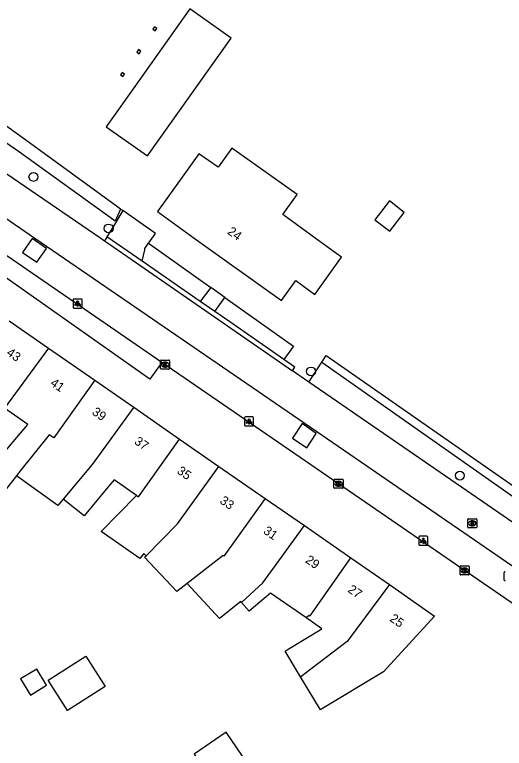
# Model space of a CAD drawing. Extents: x 163863 to 164644, y 379566 to 382155.
# Drawn here: x 164350.3 to 164404.5, y 381693.6 to 381774.7 of the extents above; entities that cross this region are included whole.
import ezdxf

# ---------------------------------------------------------------- set-up
doc = ezdxf.new("R2010")
doc.units = 0
for name, color, linetype in [('IMGEO_Boom', 7, 'Continuous'), ('IMGEO_Brandkraan', 7, 'Continuous'), ('IMGEO_Groenvoorziening', 7, 'Continuous'), ('IMGEO_Kolk', 7, 'Continuous'), ('IMGEO_Lichtpunt', 7, 'Continuous'), ('IMGEO_Pand', 7, 'Continuous'), ('IMGEO_Pand_nummerreeks', 7, 'Continuous'), ('IMGEO_Parkeervlak_open', 7, 'Continuous'), ('IMGEO_Rijbaan_lokaal_gesloten', 7, 'Continuous'), ('IMGEO_Rijbaan_lokaal_open', 7, 'Continuous'), ('IMGEO_Rioolput', 7, 'Continuous'), ('IMGEO_Voetpad_halfverhard', 7, 'Continuous'), ('IMGEO_Voetpad_open', 7, 'Continuous'), ('IMGEO_Waterloop', 7, 'Continuous')]:
    doc.layers.add(name, color=color, linetype=linetype)

msp = doc.modelspace()

# ---------------------------------------------------------------- linework, layer by layer
at = {"layer": 'IMGEO_Boom'}
for centre in [(164352.371, 381756.76), (164360.689, 381751.063), (164383.081, 381735.243), (164399.541, 381723.722)]:
    msp.add_circle(centre, 0.489, dxfattribs=at)
at = {"layer": 'IMGEO_Brandkraan'}
msp.add_line((164404.464, 381712.158), (164404.464, 381713.01), dxfattribs=at)
msp.add_lwpolyline([(164404.464, 381712.158), (164404.464, 381713.01)], dxfattribs=at)
for centre, start, end in [((164404.541, 381713.008), 91.55205, 178.44795), ((164404.541, 381713.008), 91.55205, 178.44795), ((164404.541, 381712.16), 181.55205, 268.44795), ((164404.541, 381712.16), 181.55205, 268.44795)]:
    msp.add_arc(centre, 0.0765, start, end, dxfattribs=at)
at = {"layer": 'IMGEO_Groenvoorziening'}
for points in [[(164362.264, 381753.03), (164362.019, 381753.203)], [(164365.11, 381749.429), (164371.983, 381744.544)], [(164373.541, 381743.437), (164381.128, 381738.044), (164380.075, 381736.577)], [(164382.848, 381734.057), (164384.279, 381736.27)]]:
    msp.add_lwpolyline(points, dxfattribs=at)
at = {"layer": 'IMGEO_Kolk'}
for p, q in [((164366.513, 381736.505), (164367.365, 381736.505)), ((164366.438, 381735.579), (164366.438, 381736.431)), ((164366.949, 381735.725), (164366.924, 381735.725)), ((164366.926, 381736.285), (164366.951, 381736.285)), ((164367.439, 381736.431), (164367.439, 381735.579)), ((164367.365, 381735.505), (164366.513, 381735.505)), ((164385.621, 381722.391), (164385.621, 381723.243)), ((164385.696, 381723.317), (164386.548, 381723.317)), ((164386.109, 381723.097), (164386.134, 381723.097)), ((164386.622, 381723.243), (164386.622, 381722.391)), ((164386.548, 381722.317), (164385.696, 381722.317)), ((164386.132, 381722.537), (164386.107, 381722.537)), ((164399.638, 381713.731), (164400.49, 381713.731)), ((164399.563, 381712.805), (164399.563, 381713.657)), ((164400.074, 381712.951), (164400.049, 381712.951)), ((164400.051, 381713.511), (164400.076, 381713.511)), ((164400.564, 381713.657), (164400.564, 381712.805)), ((164400.49, 381712.731), (164399.638, 381712.731))]:
    msp.add_line(p, q, dxfattribs=at)
for points in [[(164366.513, 381736.505), (164367.365, 381736.505)], [(164366.438, 381735.579), (164366.438, 381736.431)], [(164366.759, 381736.205), (164366.882, 381736.205), (164366.882, 381736.054), (164367.012, 381736.205), (164367.176, 381736.205), (164367.03, 381736.054), (164367.183, 381735.805), (164367.031, 381735.805), (164366.946, 381735.969), (164366.882, 381735.902), (164366.882, 381735.805), (164366.759, 381735.805), (164366.759, 381736.205)], [(164367.439, 381736.431), (164367.439, 381735.579)], [(164367.365, 381735.505), (164366.513, 381735.505)], [(164385.621, 381722.391), (164385.621, 381723.243)], [(164385.696, 381723.317), (164386.548, 381723.317)], [(164385.942, 381723.017), (164386.065, 381723.017), (164386.065, 381722.866), (164386.195, 381723.017), (164386.359, 381723.017), (164386.213, 381722.866), (164386.366, 381722.617), (164386.214, 381722.617), (164386.129, 381722.781), (164386.065, 381722.714), (164386.065, 381722.617), (164385.942, 381722.617), (164385.942, 381723.017)], [(164386.622, 381723.243), (164386.622, 381722.391)], [(164386.548, 381722.317), (164385.696, 381722.317)], [(164399.638, 381713.731), (164400.49, 381713.731)], [(164399.563, 381712.805), (164399.563, 381713.657)], [(164399.884, 381713.431), (164400.007, 381713.431), (164400.007, 381713.28), (164400.137, 381713.431), (164400.301, 381713.431), (164400.155, 381713.28), (164400.308, 381713.031), (164400.156, 381713.031), (164400.071, 381713.195), (164400.007, 381713.128), (164400.007, 381713.031), (164399.884, 381713.031), (164399.884, 381713.431)], [(164400.564, 381713.657), (164400.564, 381712.805)], [(164400.49, 381712.731), (164399.638, 381712.731)]]:
    msp.add_lwpolyline(points, dxfattribs=at)
for centre, start, end in [((164366.515, 381736.429), 91.55205, 178.44795), ((164366.515, 381736.429), 91.55205, 178.44795), ((164367.363, 381736.429), 1.55205, 88.44795), ((164367.363, 381736.429), 1.55205, 88.44795), ((164366.515, 381735.581), 181.55205, 268.44795), ((164366.515, 381735.581), 181.55205, 268.44795), ((164367.363, 381735.581), 271.55205, 358.44795), ((164367.363, 381735.581), 271.55205, 358.44795), ((164385.698, 381723.241), 91.55205, 178.44795), ((164385.698, 381723.241), 91.55205, 178.44795), ((164386.546, 381723.241), 1.55205, 88.44795), ((164386.546, 381723.241), 1.55205, 88.44795), ((164385.698, 381722.393), 181.55205, 268.44795), ((164385.698, 381722.393), 181.55205, 268.44795), ((164386.546, 381722.393), 271.55205, 358.44795), ((164386.546, 381722.393), 271.55205, 358.44795), ((164399.64, 381713.655), 91.55205, 178.44795), ((164399.64, 381713.655), 91.55205, 178.44795), ((164400.488, 381713.655), 1.55205, 88.44795), ((164400.488, 381713.655), 1.55205, 88.44795), ((164399.64, 381712.807), 181.55205, 268.44795), ((164399.64, 381712.807), 181.55205, 268.44795), ((164400.488, 381712.807), 271.55205, 358.44795), ((164400.488, 381712.807), 271.55205, 358.44795)]:
    msp.add_arc(centre, 0.0765, start, end, dxfattribs=at)
for centre, major_axis, ratio, start_param, end_param in [((164366.925, 381736.005), (-0.387, 0.002), 0.722429, 4.712389, 7.853982), ((164366.95, 381736.005), (-0.39, 0.002), 0.717154, 1.570796, 4.712389), ((164386.108, 381722.817), (-0.387, 0.002), 0.722429, 4.712389, 7.853982), ((164386.133, 381722.817), (-0.39, 0.002), 0.717154, 1.570796, 4.712389), ((164400.05, 381713.231), (-0.387, 0.002), 0.722429, 4.712389, 7.853982), ((164400.075, 381713.231), (-0.39, 0.002), 0.717154, 1.570796, 4.712389)]:
    msp.add_ellipse(centre, major_axis=major_axis, ratio=ratio, start_param=start_param, end_param=end_param, dxfattribs=at)
at = {"layer": 'IMGEO_Lichtpunt'}
for p, q in [((164356.753, 381743.16), (164356.753, 381742.353)), ((164356.753, 381743.16), (164356.753, 381742.353)), ((164357.655, 381743.255), (164356.847, 381743.255)), ((164357.655, 381743.255), (164356.847, 381743.255)), ((164357.749, 381742.353), (164357.749, 381743.16)), ((164357.749, 381742.353), (164357.749, 381743.16)), ((164356.847, 381742.259), (164357.655, 381742.259)), ((164356.847, 381742.259), (164357.655, 381742.259)), ((164375.728, 381730.112), (164375.728, 381729.305)), ((164375.728, 381730.112), (164375.728, 381729.305)), ((164376.63, 381730.207), (164375.822, 381730.207)), ((164376.63, 381730.207), (164375.822, 381730.207)), ((164376.724, 381729.305), (164376.724, 381730.112)), ((164376.724, 381729.305), (164376.724, 381730.112)), ((164375.822, 381729.211), (164376.63, 381729.211)), ((164375.822, 381729.211), (164376.63, 381729.211)), ((164395.905, 381717.012), (164395.097, 381717.012)), ((164395.905, 381717.012), (164395.097, 381717.012)), ((164395.003, 381716.917), (164395.003, 381716.11)), ((164395.003, 381716.917), (164395.003, 381716.11)), ((164395.999, 381716.11), (164395.999, 381716.917)), ((164395.999, 381716.11), (164395.999, 381716.917)), ((164395.097, 381716.016), (164395.905, 381716.016)), ((164395.097, 381716.016), (164395.905, 381716.016))]:
    msp.add_line(p, q, dxfattribs=at)
for points in [[(164357.127, 381742.824), (164357.166, 381742.796), (164356.978, 381742.534), (164356.94, 381742.561), (164357.127, 381742.824)], [(164357.229, 381742.776), (164357.276, 381742.776), (164357.276, 381742.454), (164357.229, 381742.454), (164357.229, 381742.776)], [(164357.339, 381742.796), (164357.377, 381742.823), (164357.564, 381742.561), (164357.525, 381742.533), (164357.339, 381742.796)], [(164376.102, 381729.776), (164376.141, 381729.748), (164375.953, 381729.486), (164375.915, 381729.513), (164376.102, 381729.776)], [(164376.204, 381729.728), (164376.251, 381729.728), (164376.251, 381729.406), (164376.204, 381729.406), (164376.204, 381729.728)], [(164376.314, 381729.748), (164376.352, 381729.775), (164376.539, 381729.513), (164376.5, 381729.485), (164376.314, 381729.748)], [(164395.377, 381716.581), (164395.416, 381716.553), (164395.228, 381716.291), (164395.19, 381716.318), (164395.377, 381716.581)], [(164395.479, 381716.533), (164395.526, 381716.533), (164395.526, 381716.211), (164395.479, 381716.211), (164395.479, 381716.533)], [(164395.589, 381716.553), (164395.627, 381716.58), (164395.814, 381716.318), (164395.775, 381716.29), (164395.589, 381716.553)]]:
    msp.add_lwpolyline(points, dxfattribs=at)
for centre in [(164357.252, 381742.958), (164376.227, 381729.91), (164395.502, 381716.715)]:
    msp.add_circle(centre, 0.0994, dxfattribs=at)
for centre, start, end in [((164356.847, 381743.16), 90, 180), ((164356.847, 381743.16), 90, 180), ((164357.655, 381743.16), 0, 90), ((164357.655, 381743.16), 0, 90), ((164356.847, 381742.353), 180, 270), ((164356.847, 381742.353), 180, 270), ((164357.655, 381742.353), 270, 0), ((164357.655, 381742.353), 270, 360), ((164375.822, 381730.112), 90, 180), ((164375.822, 381730.112), 90, 180), ((164376.63, 381730.112), 0, 90), ((164376.63, 381730.112), 0, 90), ((164375.822, 381729.305), 180, 270), ((164375.822, 381729.305), 180, 270), ((164376.63, 381729.305), 270, 0), ((164376.63, 381729.305), 270, 360), ((164395.097, 381716.917), 90, 180), ((164395.097, 381716.917), 90, 180), ((164395.905, 381716.917), 0, 90), ((164395.905, 381716.917), 0, 90), ((164395.097, 381716.11), 180, 270), ((164395.097, 381716.11), 180, 270), ((164395.905, 381716.11), 270, 0), ((164395.905, 381716.11), 270, 360)]:
    msp.add_arc(centre, 0.0946, start, end, dxfattribs=at)
at = {"layer": 'IMGEO_Pand'}
for points in [[(164363.402, 381766.508), (164360.427, 381762.301), (164364.99, 381759.075), (164374.23, 381772.12), (164369.661, 381775.357), (164363.402, 381766.508)], [(164365.852, 381772.92), (164366.037, 381773.182), (164365.775, 381773.367), (164365.59, 381773.105), (164365.852, 381772.92)], [(164364.06, 381770.391), (164364.245, 381770.652), (164363.984, 381770.837), (164363.799, 381770.576), (164364.06, 381770.391)], [(164362.279, 381767.877), (164362.464, 381768.139), (164362.203, 381768.324), (164362.018, 381768.062), (164362.279, 381767.877)], [(164384.356, 381749.398), (164383.526, 381750), (164379.945, 381752.598), (164381.542, 381754.8), (164374.323, 381759.95), (164372.81, 381757.83), (164370.67, 381759.324), (164368.998, 381756.992), (164366.083, 381752.929), (164370.167, 381750), (164379.821, 381743.076), (164381.407, 381745.286), (164383.511, 381743.759), (164386.461, 381747.871), (164384.356, 381749.398)], [(164390.141, 381752.016), (164391.793, 381750.742), (164393.401, 381752.828), (164391.749, 381754.101), (164390.141, 381752.016)], [(164349.676, 381740.859), (164354.042, 381737.829)], [(164354.042, 381737.829), (164349.184, 381731.176)], [(164354.042, 381737.829), (164359.164, 381734.275)], [(164359.164, 381734.275), (164354.614, 381727.882), (164354.097, 381728.241), (164350.961, 381724.279), (164350.492, 381723.687)], [(164359.164, 381734.275), (164363.467, 381731.289)], [(164350.492, 381723.687), (164348.988, 381721.786), (164348.799, 381721.652), (164346.4, 381719.939), (164344.855, 381721.269), (164351.754, 381729.39), (164349.184, 381731.176)], [(164363.467, 381731.289), (164358.862, 381724.936), (164355.658, 381721.111)], [(164363.467, 381731.289), (164368.546, 381727.764)], [(164363.776, 381721.527), (164363.998, 381721.373), (164368.546, 381727.764)], [(164368.546, 381727.764), (164372.899, 381724.743)], [(164364.832, 381714.86), (164368.328, 381718.37), (164372.899, 381724.743)], [(164372.899, 381724.743), (164378.015, 381721.193)], [(164355.658, 381721.111), (164355.072, 381720.411), (164350.492, 381723.687)], [(164363.776, 381721.527), (164361.292, 381723.25), (164360.83, 381722.692), (164360.648, 381722.472), (164357.992, 381719.262), (164355.658, 381721.111)], [(164364.832, 381714.86), (164364.572, 381715.105), (164364.139, 381714.554), (164359.852, 381717.545), (164363.776, 381721.527)], [(164378.015, 381721.193), (164373.447, 381714.819), (164373.349, 381714.887), (164369.371, 381711.799)], [(164378.015, 381721.193), (164382.346, 381718.188)], [(164375.391, 381709.7), (164377.736, 381711.844), (164382.346, 381718.188)], [(164382.346, 381718.188), (164387.477, 381714.627)], [(164369.371, 381711.799), (164368.221, 381710.906), (164364.655, 381714.683), (164364.832, 381714.86)], [(164382.491, 381708.022), (164382.888, 381708.27), (164382.979, 381708.208), (164387.477, 381714.627)], [(164387.477, 381714.627), (164391.751, 381711.661)], [(164375.391, 381709.7), (164375.31, 381709.792), (164372.95, 381707.902), (164369.371, 381711.799)], [(164391.751, 381711.661), (164387.087, 381705.358), (164382.275, 381701.725), (164382.194, 381701.664), (164381.927, 381701.462)], [(164391.751, 381711.661), (164396.75, 381708.192), (164391.116, 381702.026), (164384.351, 381697.949), (164384.116, 381697.807), (164381.927, 381701.462)], [(164382.491, 381708.022), (164378.587, 381710.736), (164376.254, 381708.729), (164375.391, 381709.7)], [(164381.927, 381701.462), (164380.218, 381704.316), (164380.541, 381704.511), (164384.291, 381706.771), (164382.491, 381708.022)], [(164356.124, 381697.732), (164353.995, 381701.098), (164358.18, 381703.745), (164360.308, 381700.379), (164356.124, 381697.732)], [(164350.949, 381701.231), (164352.039, 381699.449), (164353.829, 381700.544), (164352.739, 381702.326), (164350.949, 381701.231)], [(164370.162, 381692.907), (164374.263, 381686.925), (164377.796, 381689.347), (164373.695, 381695.329), (164370.162, 381692.907)]]:
    msp.add_lwpolyline(points, dxfattribs=at)
at = {"layer": 'IMGEO_Parkeervlak_open'}
for points in [[(164352.745, 381747.339), (164353.81, 381748.857), (164352.232, 381749.958), (164351.164, 381748.396), (164352.745, 381747.339)], [(164406.418, 381708.86), (164381.892, 381725.724), (164366.579, 381736.251)], [(164382.6, 381726.798), (164383.658, 381728.376), (164382.102, 381729.474), (164381.029, 381727.867), (164382.6, 381726.798)]]:
    msp.add_lwpolyline(points, dxfattribs=at)
at = {"layer": 'IMGEO_Rijbaan_lokaal_gesloten'}
for points in [[(164324.169, 381774.363), (164359.822, 381750), (164360.25, 381749.708)], [(164324.768, 381769.068), (164352.536, 381750), (164383.72, 381728.586), (164408.346, 381711.663)], [(164360.25, 381749.708), (164360.792, 381749.337), (164381.018, 381735.317)], [(164382.848, 381734.057), (164381.018, 381735.317)], [(164410.608, 381714.952), (164385.909, 381731.949), (164382.848, 381734.057)]]:
    msp.add_lwpolyline(points, dxfattribs=at)
at = {"layer": 'IMGEO_Rijbaan_lokaal_open'}
for points in [[(164362.264, 381753.03), (164361.118, 381751.14), (164360.511, 381750.139)], [(164365.11, 381749.429), (164365.15, 381749.485), (164365.86, 381750.491), (164362.264, 381753.03)], [(164364.415, 381747.432), (164360.511, 381750.139)], [(164364.415, 381747.432), (164364.689, 381748.711), (164364.703, 381748.852), (164365.11, 381749.429)]]:
    msp.add_lwpolyline(points, dxfattribs=at)
at = {"layer": 'IMGEO_Rioolput'}
for p, q in [((164400.417, 381718.026), (164400.417, 381718.878)), ((164400.492, 381718.952), (164401.344, 381718.952)), ((164400.905, 381718.732), (164400.93, 381718.732)), ((164401.418, 381718.878), (164401.418, 381718.026)), ((164401.344, 381717.952), (164400.492, 381717.952)), ((164400.928, 381718.172), (164400.903, 381718.172))]:
    msp.add_line(p, q, dxfattribs=at)
for points in [[(164400.417, 381718.026), (164400.417, 381718.878)], [(164400.492, 381718.952), (164401.344, 381718.952)], [(164401.006, 381718.65), (164400.754, 381718.652), (164400.754, 381718.252)], [(164401.418, 381718.878), (164401.418, 381718.026)], [(164401.344, 381717.952), (164400.492, 381717.952)], [(164400.754, 381718.252), (164400.878, 381718.252), (164400.878, 381718.414), (164400.889, 381718.414)], [(164400.932, 381718.571), (164400.878, 381718.571), (164400.878, 381718.49)], [(164400.878, 381718.49), (164400.93, 381718.49)], [(164400.936, 381718.385), (164401.007, 381718.252), (164401.147, 381718.252), (164401.082, 381718.378)]]:
    msp.add_lwpolyline(points, dxfattribs=at)
for centre, radius, start, end in [((164400.494, 381718.876), 0.0765, 91.55205, 178.44795), ((164400.494, 381718.876), 0.0765, 91.55205, 178.44795), ((164401.005, 381718.54), 0.109, 350.36119, 89.41601), ((164401.342, 381718.876), 0.0765, 1.55205, 88.44795), ((164401.342, 381718.876), 0.0765, 1.55205, 88.44795), ((164400.494, 381718.028), 0.0765, 181.55205, 268.44795), ((164400.494, 381718.028), 0.0765, 181.55205, 268.44795), ((164400.888, 381718.361), 0.0533, 26.02933, 88.69889), ((164400.914, 381718.679), 0.19, 274.7715, 282.96867), ((164400.938, 381718.475), 0.0964, 77.00612, 93.18647), ((164400.952, 381718.532), 0.0378, 276.66336, 79.67722), ((164401.003, 381718.54), 0.112, 277.58423, 350.98172), ((164400.987, 381718.325), 0.108, 29.51342, 73.79051), ((164401.342, 381718.028), 0.0765, 271.55205, 358.44795), ((164401.342, 381718.028), 0.0765, 271.55205, 358.44795)]:
    msp.add_arc(centre, radius, start, end, dxfattribs=at)
for centre, major_axis, ratio, start_param, end_param in [((164400.904, 381718.452), (-0.387, 0.002), 0.722429, 4.712389, 7.853982), ((164400.929, 381718.452), (-0.39, 0.002), 0.717154, 1.570796, 4.712389)]:
    msp.add_ellipse(centre, major_axis=major_axis, ratio=ratio, start_param=start_param, end_param=end_param, dxfattribs=at)
at = {"layer": 'IMGEO_Voetpad_halfverhard'}
for points in [[(164360.511, 381750.139), (164360.489, 381750.103), (164360.25, 381749.708)], [(164370.827, 381742.988), (164370.817, 381742.995), (164364.415, 381747.432)], [(164380.075, 381736.577), (164379.696, 381736.84), (164374.088, 381740.727), (164372.441, 381741.869)], [(164381.018, 381735.317), (164381.302, 381735.727), (164380.075, 381736.577)]]:
    msp.add_lwpolyline(points, dxfattribs=at)
at = {"layer": 'IMGEO_Voetpad_open'}
for points in [[(164366.579, 381736.251), (164365.238, 381734.407), (164343.09, 381750), (164341.646, 381751.017), (164341.728, 381751.199), (164335.582, 381755.465), (164335.669, 381755.626), (164322.057, 381765.024), (164322.896, 381766.247)], [(164366.579, 381736.251), (164346.556, 381750), (164322.896, 381766.247)], [(164371.983, 381744.544), (164370.827, 381742.988)], [(164373.541, 381743.437), (164371.983, 381744.544)], [(164372.441, 381741.869), (164370.827, 381742.988)], [(164372.441, 381741.869), (164373.541, 381743.437)]]:
    msp.add_lwpolyline(points, dxfattribs=at)
at = {"layer": 'IMGEO_Waterloop'}
for points in [[(164362.019, 381753.203), (164361.428, 381751.86), (164361.269, 381751.975), (164350.837, 381759.485), (164291.421, 381800.511), (164261.825, 381821.183), (164221.968, 381849.023), (164223.061, 381850.617)], [(164362.019, 381753.203), (164361.552, 381753.543), (164351.545, 381760.837), (164333.203, 381774.002)], [(164384.279, 381736.27), (164384.767, 381737.008), (164412.499, 381717.701), (164442.345, 381696.707), (164442.313, 381695.498)], [(164384.279, 381736.27), (164411.916, 381716.853), (164441.971, 381695.738)]]:
    msp.add_lwpolyline(points, dxfattribs=at)

# ---------------------------------------------------------------- texts
at = {"layer": 'IMGEO_Pand_nummerreeks'}
for s, rotation, p in [('24', 324.34689, (164373.75, 381750.532)), ('43', 325.24438, (164349.31, 381737.12)), ('41', 325.24438, (164354.147, 381733.763)), ('39', 325.24438, (164358.766, 381730.558)), ('37', 325.24438, (164363.457, 381727.303)), ('35', 325.24155, (164368.173, 381724.03)), ('33', 325.24438, (164372.908, 381720.744)), ('31', 325.24155, (164377.724, 381717.402)), ('29', 325.24155, (164382.362, 381714.184)), ('27', 325.24438, (164387.065, 381710.92)), ('25', 325.24438, (164391.701, 381707.703))]:
    msp.add_text(s, height=1, rotation=rotation, dxfattribs=at).set_placement(p)

doc.saveas('drawing.dxf')
